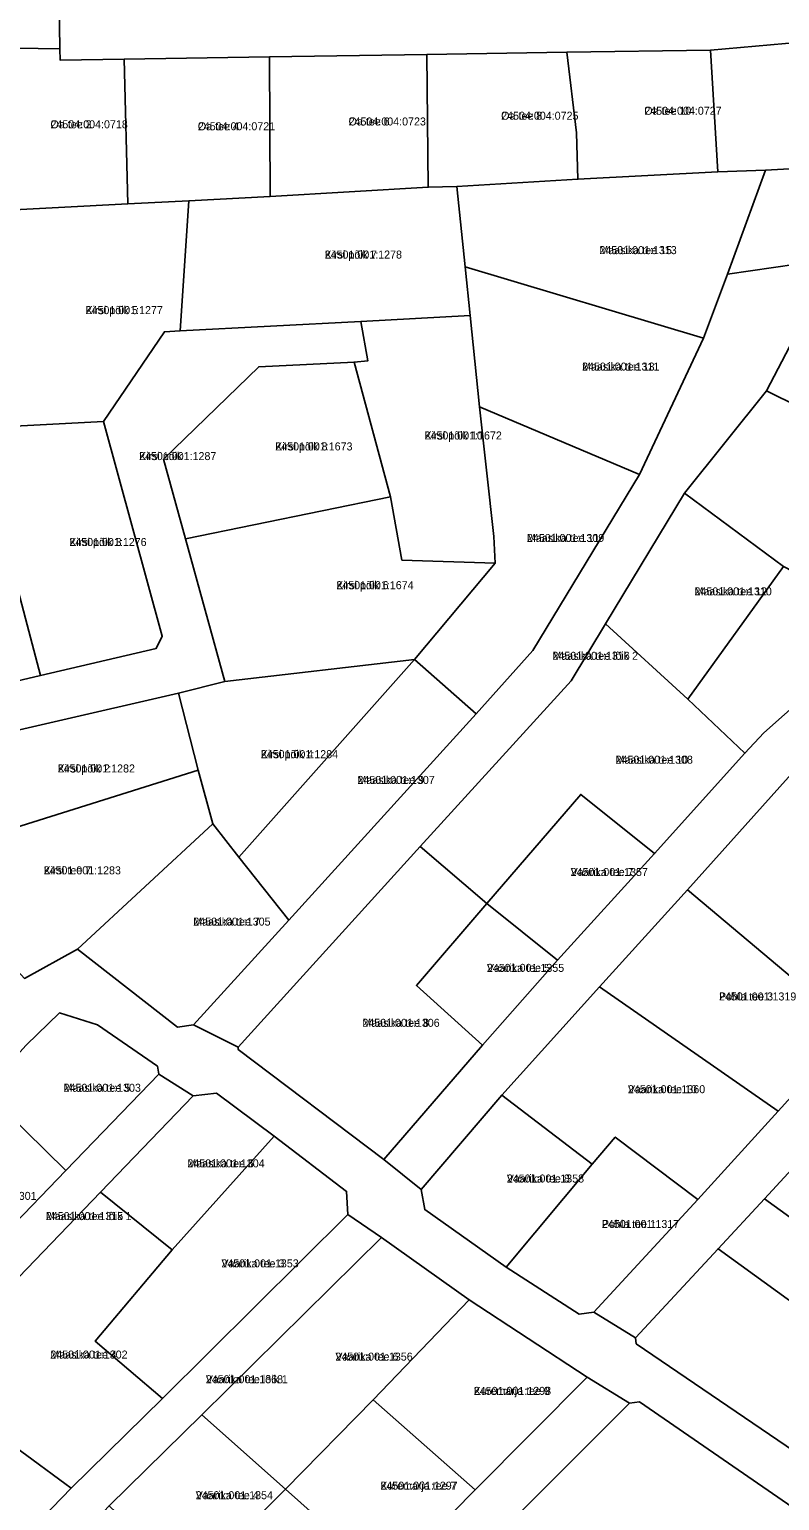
# Model space of a CAD drawing. Extents: x 551291 to 575799, y 6581704 to 6610137.
# Drawn here: x 559102.6 to 559243.4, y 6593937.5 to 6594213.3 of the extents above; entities that cross this region are included whole.
import ezdxf

# ---------------------------------------------------------------- set-up
doc = ezdxf.new("R2010")
doc.units = 0
for name, color, linetype in [('L_AADRESS', 7, 'Continuous'), ('PIIR', 7, 'Continuous'), ('TUNNUS', 7, 'Continuous')]:
    doc.layers.add(name, color=color, linetype=linetype)

msp = doc.modelspace()

# ---------------------------------------------------------------- linework, layer by layer
at = {"layer": 'PIIR'}
for points in [[(559091.89, 6594269.57), (559107.32, 6594269.22), (559107.35, 6594262.67), (559119.31, 6594262.74), (559119.35, 6594241.61), (559119.43, 6594238.08), (559112.4, 6594234.58), (559109.26, 6594228.91), (559109.56, 6594222.81), (559108.17, 6594222.79), (559108.36, 6594209.68), (559092.07, 6594209.91), (559091.93, 6594221.53), (559091.75, 6594237.49), (559091.55, 6594263.8)], [(559230.42, 6594209.43), (559255.79, 6594211.66), (559256.4, 6594187.84), (559240.77, 6594186.97), (559231.8, 6594186.64)], [(559092.07, 6594209.91), (559108.36, 6594209.68), (559108.39, 6594207.58), (559120.38, 6594207.76), (559121.09, 6594180.66), (559093.81, 6594179.19), (559092.71, 6594192.66), (559092.1, 6594209.03)], [(559120.38, 6594207.76), (559147.66, 6594208.18), (559147.79, 6594181.99), (559132.51, 6594181.19), (559121.09, 6594180.66)], [(559147.66, 6594208.18), (559177.17, 6594208.65), (559177.45, 6594183.74), (559147.79, 6594181.99)], [(559177.17, 6594208.65), (559203.44, 6594209.05), (559205.29, 6594193.94), (559205.54, 6594185.24), (559182.83, 6594183.89), (559177.45, 6594183.74)], [(559203.44, 6594209.05), (559230.42, 6594209.43), (559231.8, 6594186.64), (559205.54, 6594185.24), (559205.29, 6594193.94)], [(559184.41, 6594168.82), (559182.83, 6594183.89), (559205.54, 6594185.24), (559231.8, 6594186.64), (559240.77, 6594186.97), (559233.63, 6594167.43), (559229.13, 6594155.42)], [(559240.77, 6594186.97), (559256.4, 6594187.84), (559272.3, 6594188.24), (559272.53, 6594180.18), (559268.32, 6594180.11), (559268.14, 6594172.42), (559233.63, 6594167.43)], [(559130.94, 6594156.84), (559132.51, 6594181.19), (559147.79, 6594181.99), (559177.45, 6594183.74), (559182.83, 6594183.89), (559184.41, 6594168.82), (559185.33, 6594159.67), (559164.79, 6594158.57)], [(559094.52, 6594161.53), (559093.81, 6594179.19), (559121.09, 6594180.66), (559132.51, 6594181.19), (559130.94, 6594156.84), (559127.94, 6594156.64), (559116.52, 6594139.85), (559097.53, 6594138.82)], [(559141.77, 6594022.54), (559133.39, 6594026.69), (559151.28, 6594046.35), (559186.46, 6594085.05), (559197.1, 6594096.92), (559217.09, 6594129.91), (559229.13, 6594155.42), (559233.63, 6594167.43), (559268.14, 6594172.42), (559268.03, 6594167.56), (559251.07, 6594164.93), (559240.92, 6594145.6), (559225.55, 6594126.37), (559210.74, 6594101.87), (559204.3, 6594091.2), (559175.94, 6594060.13)], [(559185.33, 6594159.67), (559184.41, 6594168.82), (559229.13, 6594155.42), (559217.09, 6594129.91), (559187.09, 6594142.57)], [(559240.92, 6594145.6), (559251.07, 6594164.93), (559268.03, 6594167.56), (559289.26, 6594168.57), (559281.29, 6594156.31), (559265.69, 6594133.31)], [(559176.16, 6593995.86), (559169.11, 6594001.47), (559187.62, 6594022.9), (559201.71, 6594038.84), (559219.93, 6594058.81), (559236.88, 6594077.64), (559240.46, 6594081.45), (559262.6, 6594101.09), (559284.55, 6594123.76), (559303.46, 6594141.55), (559323.46, 6594164.39), (559334.22, 6594162.81), (559320.79, 6594147.7), (559310.88, 6594136.93), (559299.37, 6594125.45), (559268.46, 6594094.04), (559246.72, 6594074.98), (559226.13, 6594052.02), (559209.61, 6594033.82), (559191.25, 6594013.56)], [(559083.08, 6594077.93), (559082.35, 6594076.77), (559080.27, 6594087.34), (559081.32, 6594086.72), (559104.68, 6594092.19), (559126.41, 6594097.28), (559127.56, 6594099.61), (559116.52, 6594139.85), (559127.94, 6594156.64), (559130.94, 6594156.84), (559164.79, 6594158.57), (559166.12, 6594151.18), (559163.54, 6594150.97), (559145.65, 6594150.08), (559127.76, 6594132.76), (559131.94, 6594117.82), (559139.27, 6594091.06), (559130.58, 6594088.89)], [(559166.12, 6594151.18), (559164.79, 6594158.57), (559185.33, 6594159.67), (559187.09, 6594142.57), (559189.8, 6594118.26), (559190, 6594113.27), (559172.53, 6594113.83), (559170.41, 6594125.72), (559163.54, 6594150.97)], [(559131.94, 6594117.82), (559127.76, 6594132.76), (559145.65, 6594150.08), (559163.54, 6594150.97), (559170.41, 6594125.72)], [(559225.55, 6594126.37), (559240.92, 6594145.6), (559265.69, 6594133.31), (559249.84, 6594109.71), (559244.12, 6594112.66)], [(559189.8, 6594118.26), (559187.09, 6594142.57), (559217.09, 6594129.91), (559197.1, 6594096.92), (559186.46, 6594085.05), (559174.86, 6594095.23), (559190, 6594113.27)], [(559104.68, 6594092.19), (559092.66, 6594137.82), (559097.53, 6594138.82), (559116.52, 6594139.85), (559127.56, 6594099.61), (559126.41, 6594097.28)], [(559080.27, 6594087.34), (559070.32, 6594132.79), (559092.66, 6594137.82), (559104.68, 6594092.19), (559081.32, 6594086.72)], [(559139.27, 6594091.06), (559131.94, 6594117.82), (559170.41, 6594125.72), (559172.53, 6594113.83), (559190, 6594113.27), (559174.86, 6594095.23)], [(559210.74, 6594101.87), (559225.55, 6594126.37), (559244.12, 6594112.66), (559226.18, 6594087.74)], [(559236.88, 6594077.64), (559226.18, 6594087.74), (559244.12, 6594112.66), (559249.84, 6594109.71), (559262.6, 6594101.09), (559240.46, 6594081.45)], [(559204.3, 6594091.2), (559210.74, 6594101.87), (559226.18, 6594087.74), (559236.88, 6594077.64), (559219.93, 6594058.81), (559206.09, 6594069.9), (559188.43, 6594049.47), (559175.94, 6594060.13)], [(559134.29, 6594074.43), (559130.58, 6594088.89), (559139.27, 6594091.06), (559174.86, 6594095.23), (559141.9, 6594058.18), (559137.01, 6594064.38)], [(559151.28, 6594046.35), (559141.9, 6594058.18), (559174.86, 6594095.23), (559186.46, 6594085.05)], [(559216.33, 6593968.06), (559208.51, 6593972.88), (559228.04, 6593993.97), (559243.12, 6594010.55), (559257.11, 6594025.97), (559278.13, 6594049.31), (559296.09, 6594070.61), (559305.45, 6594081.11), (559299.94, 6594085.85), (559308.74, 6594096.28), (559314.57, 6594090.74), (559322.35, 6594086.1), (559312.44, 6594075.24), (559303.19, 6594065.05), (559293.53, 6594054.14), (559284.72, 6594043.28), (559275.28, 6594032.28), (559267.25, 6594023.67), (559258.44, 6594013.84), (559249.43, 6594003.75), (559240.57, 6593994.11), (559231.85, 6593984.75)], [(559082.35, 6594076.77), (559083.08, 6594077.93), (559130.58, 6594088.89), (559134.29, 6594074.43), (559085.48, 6594059.17)], [(559083.32, 6594055.44), (559085.48, 6594059.17), (559134.29, 6594074.43), (559137.01, 6594064.38), (559111.64, 6594040.93), (559101.69, 6594035.42)], [(559257.11, 6594025.97), (559226.13, 6594052.02), (559246.72, 6594074.98), (559278.13, 6594049.31)], [(559201.71, 6594038.84), (559188.43, 6594049.47), (559206.09, 6594069.9), (559219.93, 6594058.81)], [(559130.43, 6594026.26), (559111.64, 6594040.93), (559137.01, 6594064.38), (559141.9, 6594058.18), (559151.28, 6594046.35), (559133.39, 6594026.69)], [(559141.82, 6594022.07), (559141.77, 6594022.54), (559175.94, 6594060.13), (559188.43, 6594049.47), (559175.23, 6594034.11), (559187.62, 6594022.9), (559169.11, 6594001.47)], [(559243.12, 6594010.55), (559209.61, 6594033.82), (559226.13, 6594052.02), (559257.11, 6594025.97)], [(559187.62, 6594022.9), (559175.23, 6594034.11), (559188.43, 6594049.47), (559201.71, 6594038.84)], [(559208.25, 6594000.59), (559191.25, 6594013.56), (559209.61, 6594033.82), (559243.12, 6594010.55), (559228.04, 6593993.97), (559212.55, 6594005.67)], [(559109.44, 6593999.39), (559094.22, 6594014.32), (559102.03, 6594022.89), (559108.29, 6594028.94), (559115.42, 6594026.72), (559126.66, 6594018.97), (559126.89, 6594017.48)], [(559083.68, 6593961.87), (559078.07, 6593967.3), (559084.08, 6593973.08), (559109.44, 6593999.39), (559126.89, 6594017.48), (559133.35, 6594013.41), (559115.99, 6593995.38)], [(559084.08, 6593973.08), (559069.51, 6593987.27), (559094.22, 6594014.32), (559109.44, 6593999.39)], [(559129.39, 6593984.52), (559115.99, 6593995.38), (559133.35, 6594013.41), (559137.72, 6594013.92), (559148.52, 6594005.87)], [(559176.82, 6593992.09), (559176.16, 6593995.86), (559191.25, 6594013.56), (559208.25, 6594000.59), (559192.06, 6593981.32)], [(559127.58, 6593956.67), (559114.93, 6593967.42), (559129.39, 6593984.52), (559148.52, 6594005.87), (559162.14, 6593995.49), (559162.37, 6593991.17)], [(559205.78, 6593972.47), (559192.06, 6593981.32), (559208.25, 6594000.59), (559212.55, 6594005.67), (559228.04, 6593993.97), (559208.51, 6593972.88)], [(559295.57, 6593954.38), (559240.57, 6593994.11), (559249.43, 6594003.75), (559302.54, 6593965.43)], [(559093.75, 6593952.11), (559083.68, 6593961.87), (559115.99, 6593995.38), (559129.39, 6593984.52), (559114.93, 6593967.42), (559127.58, 6593956.67), (559110.45, 6593939.88)], [(559288.65, 6593943.64), (559231.85, 6593984.75), (559240.57, 6593994.11), (559295.57, 6593954.38), (559292.49, 6593949.23)], [(559106.24, 6593930.2), (559103.32, 6593932.48), (559110.45, 6593939.88), (559127.58, 6593956.67), (559162.37, 6593991.17), (559168.66, 6593986.87), (559134.95, 6593953.59), (559117.57, 6593936.55), (559109.37, 6593927.89)], [(559150.68, 6593939.65), (559134.95, 6593953.59), (559168.66, 6593986.87), (559185.12, 6593975.18), (559167.13, 6593956.42)], [(559216.48, 6593966.93), (559216.33, 6593968.06), (559231.85, 6593984.75), (559288.65, 6593943.64), (559277.28, 6593925.6)], [(559186.26, 6593939.52), (559167.13, 6593956.42), (559185.12, 6593975.18), (559207.3, 6593960.67)], [(559110.15, 6593857.43), (559104.5, 6593860.91), (559123.24, 6593879.77), (559139.5, 6593892.66), (559152.11, 6593905.34), (559169.67, 6593922.74), (559186.26, 6593939.52), (559207.3, 6593960.67), (559215.23, 6593955.78), (559189.1, 6593929.66), (559174.61, 6593915.19), (559145.8, 6593886.2)], [(559169.67, 6593922.74), (559150.68, 6593939.65), (559167.13, 6593956.42), (559186.26, 6593939.52)], [(559208.87, 6593912.05), (559189.1, 6593929.66), (559215.23, 6593955.78), (559217.11, 6593956.06), (559254.15, 6593930.55), (559254.43, 6593927.81), (559218.03, 6593893.87), (559203.42, 6593906.86)], [(559084.64, 6593907.29), (559067.14, 6593920.06), (559093.75, 6593952.11), (559110.45, 6593939.88), (559103.32, 6593932.48), (559106.24, 6593930.2)], [(559132.85, 6593922), (559117.57, 6593936.55), (559134.95, 6593953.59), (559150.68, 6593939.65)], [(559152.11, 6593905.34), (559132.85, 6593922), (559150.68, 6593939.65), (559169.67, 6593922.74)]]:
    msp.add_lwpolyline(points, close=True, dxfattribs=at)
for points in [[(559313.5, 6594213.53), (559313.6, 6594209.89), (559287.3, 6594211.98), (559285.04, 6594212.04), (559279.49, 6594211.99), (559255.79, 6594211.66), (559230.42, 6594209.43), (559203.44, 6594209.05), (559177.17, 6594208.65), (559147.66, 6594208.18), (559120.38, 6594207.76), (559108.39, 6594207.58), (559108.36, 6594209.68), (559108.17, 6594222.79)], [(559101.69, 6594035.42), (559111.64, 6594040.93), (559130.43, 6594026.26), (559133.39, 6594026.69), (559141.77, 6594022.54), (559141.82, 6594022.07), (559169.11, 6594001.47), (559176.16, 6593995.86), (559176.82, 6593992.09), (559192.06, 6593981.32), (559205.78, 6593972.47), (559208.51, 6593972.88), (559216.33, 6593968.06), (559216.48, 6593966.93), (559277.28, 6593925.6)], [(559254.15, 6593930.55), (559217.11, 6593956.06), (559215.23, 6593955.78), (559207.3, 6593960.67), (559185.12, 6593975.18), (559168.66, 6593986.87), (559162.37, 6593991.17), (559162.14, 6593995.49), (559148.52, 6594005.87), (559137.72, 6594013.92), (559133.35, 6594013.41), (559126.89, 6594017.48), (559126.66, 6594018.97), (559115.42, 6594026.72), (559108.29, 6594028.94), (559102.03, 6594022.89), (559094.22, 6594014.32), (559069.51, 6593987.27), (559052.76, 6593968.98), (559044.72, 6593960.18), (559033.92, 6593954.49), (559012.67, 6593936.38)]]:
    msp.add_lwpolyline(points, dxfattribs=at)

# ---------------------------------------------------------------- texts
at = {"layer": 'L_AADRESS'}
for s, p in [('Oa tee 6', (559162.52, 6594195.32)), ('Oa tee 8', (559191.15, 6594196.4)), ('Oa tee 10', (559218.01, 6594197.33)), ('Oa tee 2', (559106.58, 6594194.79)), ('Oa tee 4', (559134.23, 6594194.42)), ('Kirsi põik 7', (559158.03, 6594170.37)), ('Maasika tee 15', (559209.58, 6594171.2)), ('Kirsi põik 5', (559113.16, 6594159.95)), ('Maasika tee 13', (559206.33, 6594149.37)), ('Kirsi põik 8', (559148.75, 6594134.4)), ('Kirsi põik 10', (559176.77, 6594136.45)), ('Kirsi põik', (559123.2, 6594132.59)), ('Kirsi põik 3', (559110.11, 6594116.48)), ('Maasika tee 11', (559195.98, 6594117.24)), ('Kirsi põik 6', (559160.21, 6594108.39)), ('Maasika tee 12', (559227.43, 6594107.23)), ('Maasika tee lõik 2', (559200.77, 6594095.15)), ('Kirsi põik 4', (559146.04, 6594076.71)), ('Kirsi põik 2', (559107.92, 6594074.03)), ('Maasika tee 10', (559212.62, 6594075.67)), ('Maasika tee 9', (559164.18, 6594071.88)), ('Kirsi tee 7', (559105.29, 6594054.93)), ('Vaarika tee 7', (559204.18, 6594054.62)), ('Maasika tee 7', (559133.37, 6594045.32)), ('Vaarika tee 5', (559188.47, 6594036.65)), ('Pohla tee 3', (559232.02, 6594031.29)), ('Maasika tee 8', (559165.1, 6594026.35)), ('Maasika tee 5', (559109.04, 6594014.17)), ('Vaarika tee 10', (559214.93, 6594013.9)), ('Maasika tee 6', (559132.26, 6594000)), ('Vaarika tee 8', (559192.2, 6593997.16)), ('Maasika tee lõik 1', (559105.71, 6593990.12)), ('Pohla tee 1', (559210.05, 6593988.63)), ('Vaarika tee 3', (559138.65, 6593981.25)), ('Maasika tee 4', (559106.54, 6593964.16)), ('Vaarika tee 6', (559160.04, 6593963.77)), ('Vaarika tee lõik 1', (559135.72, 6593959.53)), ('Kuremarja tee 9', (559186.01, 6593957.35)), ('Kuremarja tee 7', (559168.48, 6593939.58)), ('Vaarika tee 4', (559133.82, 6593937.79))]:
    msp.add_text(s, height=1.5, dxfattribs=at).set_placement(p)
at = {"layer": 'TUNNUS'}
for s, p in [('24504:004:0723', (559162.52, 6594195.32)), ('24504:004:0725', (559191.15, 6594196.4)), ('24504:004:0727', (559218.01, 6594197.33)), ('24504:004:0718', (559106.58, 6594194.79)), ('24504:004:0721', (559134.23, 6594194.42)), ('24501:001:1278', (559158.03, 6594170.37)), ('24501:001:1313', (559209.58, 6594171.2)), ('24501:001:1277', (559113.16, 6594159.95)), ('24501:001:1311', (559206.33, 6594149.37)), ('24501:001:1672', (559176.77, 6594136.45)), ('24501:001:1287', (559123.2, 6594132.59)), ('24501:001:1673', (559148.75, 6594134.4)), ('24501:001:1276', (559110.11, 6594116.48)), ('24501:001:1309', (559195.98, 6594117.24)), ('24501:001:1674', (559160.21, 6594108.39)), ('24501:001:1310', (559227.43, 6594107.23)), ('24501:001:1316', (559200.77, 6594095.15)), ('24501:001:1284', (559146.04, 6594076.71)), ('24501:001:1282', (559107.92, 6594074.03)), ('24501:001:1308', (559212.62, 6594075.67)), ('24501:001:1307', (559164.18, 6594071.88)), ('24501:001:1283', (559105.29, 6594054.93)), ('24501:001:1357', (559204.18, 6594054.62)), ('24501:001:1305', (559133.37, 6594045.32)), ('24501:001:1355', (559188.47, 6594036.65)), ('24501:001:1319', (559232.02, 6594031.29)), ('24501:001:1306', (559165.1, 6594026.35)), ('24501:001:1303', (559109.04, 6594014.17)), ('24501:001:1360', (559214.93, 6594013.9)), ('24501:001:1304', (559132.26, 6594000)), ('24501:001:1358', (559192.2, 6593997.16)), ('24501:001:1301', (559089.47, 6593993.9)), ('24501:001:1315', (559105.71, 6593990.12)), ('24501:001:1317', (559210.05, 6593988.63)), ('24501:001:1353', (559138.65, 6593981.25)), ('24501:001:1302', (559106.54, 6593964.16)), ('24501:001:1356', (559160.04, 6593963.77)), ('24501:001:1368', (559135.72, 6593959.53)), ('24501:001:1298', (559186.01, 6593957.35)), ('24501:001:1297', (559168.48, 6593939.58)), ('24501:001:1354', (559133.82, 6593937.79))]:
    msp.add_text(s, height=1.5, dxfattribs=at).set_placement(p)

doc.saveas('drawing.dxf')
